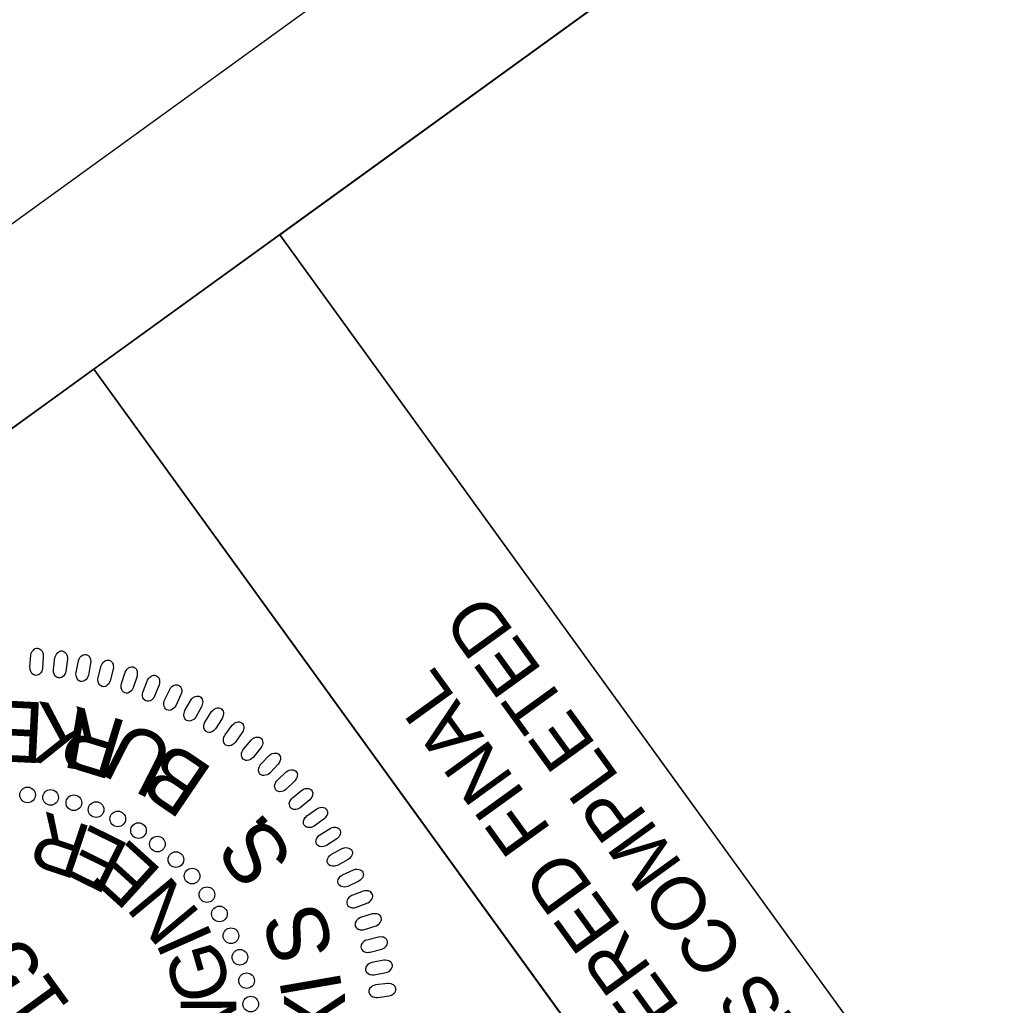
# Model space of a CAD drawing. Extents: x 474248 to 476123, y 501895 to 503900.
# Drawn here: x 474390.5 to 474491.3, y 503280.5 to 503381.5 of the extents above; entities that cross this region are included whole.
import ezdxf

# ---------------------------------------------------------------- set-up
doc = ezdxf.new("R2010")
doc.units = 0
for name, color, linetype in [('Scratch_Level_5', 7, 'Continuous'), ('Sheet Layout Plan Border', 7, 'Continuous'), ('Sheet PE Seal Cell', 7, 'Continuous'), ('Sheet Plan CELL', 7, 'Continuous'), ('Sheet Plot Border Outside CELL', 7, 'Continuous'), ('Sheet Sticker Exception Certification CELL', 7, 'Continuous'), ('Sheet Sticker Incomplete CELL', 7, 'Continuous')]:
    doc.layers.add(name, color=color, linetype=linetype)

msp = doc.modelspace()

# ---------------------------------------------------------------- linework, layer by layer
at = {"layer": 'Scratch_Level_5'}
msp.add_lwpolyline([(474627.91, 502772.46), (474393.92, 503095.62), (474534.48, 503197.42), (474417.16, 503359.44), (475062.24, 503826.52), (475162.27, 503688.38), (475227.09, 503735.31), (475493.16, 503367.85)], close=True, dxfattribs=at)
at = {"layer": 'Sheet Layout Plan Border'}
msp.add_lwpolyline([(475148.79, 502314.89), (475799.67, 502786.07), (475874.95, 502840.56), (475397.53, 503499.92), (475353.89, 503468.32), (475265.23, 503590.78), (475283.66, 503604.12), (475199.91, 503719.79), (475161.57, 503692.03), (475161.57, 503692.03), (475161.57, 503692.03), (475161.57, 503692.03), (475161.57, 503692.03), (475063.52, 503827.46), (474417.16, 503359.44), (474534.48, 503197.42), (474393.91, 503095.62), (475024.42, 502224.85)], close=True, dxfattribs=at)
at = {"layer": 'Sheet PE Seal Cell'}
for points in [[(474391.59, 503315.12), (474391.67, 503316.35), (474391.72, 503316.56), (474391.78, 503316.7), (474391.91, 503316.86), (474392.01, 503316.97), (474392.13, 503317.04), (474392.24, 503317.07), (474392.35, 503317.08), (474392.46, 503317.06), (474392.58, 503317.02), (474392.68, 503316.95), (474392.78, 503316.85), (474392.83, 503316.76), (474392.89, 503316.61), (474392.94, 503316.43), (474392.95, 503316.27), (474392.87, 503315.01), (474392.84, 503314.84), (474392.79, 503314.71), (474392.69, 503314.55), (474392.57, 503314.42), (474392.46, 503314.35), (474392.3, 503314.3), (474392.15, 503314.29), (474392.01, 503314.34), (474391.91, 503314.39), (474391.78, 503314.5), (474391.68, 503314.68), (474391.62, 503314.86), (474391.6, 503314.99)], [(474394, 503314.9), (474394.15, 503316.11), (474394.22, 503316.32), (474394.29, 503316.46), (474394.42, 503316.61), (474394.53, 503316.71), (474394.65, 503316.77), (474394.76, 503316.8), (474394.87, 503316.8), (474394.98, 503316.77), (474395.1, 503316.72), (474395.19, 503316.65), (474395.28, 503316.54), (474395.33, 503316.45), (474395.38, 503316.3), (474395.42, 503316.11), (474395.42, 503315.95), (474395.27, 503314.7), (474395.22, 503314.54), (474395.16, 503314.4), (474395.05, 503314.26), (474394.92, 503314.13), (474394.82, 503314.07), (474394.65, 503314.03), (474394.5, 503314.03), (474394.36, 503314.08), (474394.26, 503314.15), (474394.15, 503314.26), (474394.05, 503314.45), (474394.01, 503314.63), (474393.99, 503314.76)], [(474396.31, 503314.58), (474396.54, 503315.79), (474396.62, 503316), (474396.7, 503316.12), (474396.84, 503316.27), (474396.96, 503316.36), (474397.08, 503316.41), (474397.19, 503316.43), (474397.31, 503316.43), (474397.42, 503316.39), (474397.53, 503316.34), (474397.62, 503316.26), (474397.7, 503316.14), (474397.75, 503316.05), (474397.78, 503315.89), (474397.81, 503315.71), (474397.8, 503315.55), (474397.57, 503314.31), (474397.52, 503314.15), (474397.44, 503314.02), (474397.33, 503313.88), (474397.19, 503313.76), (474397.08, 503313.7), (474396.91, 503313.67), (474396.76, 503313.68), (474396.62, 503313.75), (474396.53, 503313.82), (474396.42, 503313.94), (474396.34, 503314.13), (474396.31, 503314.32), (474396.3, 503314.45)], [(474398.57, 503314.08), (474398.88, 503315.26), (474398.97, 503315.47), (474399.05, 503315.59), (474399.2, 503315.73), (474399.32, 503315.81), (474399.45, 503315.86), (474399.56, 503315.87), (474399.68, 503315.86), (474399.78, 503315.81), (474399.89, 503315.75), (474399.98, 503315.67), (474400.05, 503315.55), (474400.09, 503315.45), (474400.12, 503315.29), (474400.13, 503315.1), (474400.11, 503314.94), (474399.8, 503313.73), (474399.74, 503313.57), (474399.66, 503313.44), (474399.53, 503313.31), (474399.39, 503313.2), (474399.28, 503313.15), (474399.11, 503313.13), (474398.96, 503313.15), (474398.83, 503313.23), (474398.74, 503313.3), (474398.64, 503313.43), (474398.57, 503313.62), (474398.55, 503313.81), (474398.55, 503313.95)], [(474400.95, 503313.45), (474401.34, 503314.62), (474401.44, 503314.81), (474401.53, 503314.93), (474401.69, 503315.06), (474401.82, 503315.13), (474401.95, 503315.17), (474402.06, 503315.18), (474402.17, 503315.16), (474402.27, 503315.11), (474402.38, 503315.04), (474402.46, 503314.95), (474402.53, 503314.82), (474402.56, 503314.73), (474402.58, 503314.57), (474402.58, 503314.38), (474402.55, 503314.22), (474402.17, 503313.02), (474402.09, 503312.87), (474402.01, 503312.75), (474401.87, 503312.63), (474401.72, 503312.53), (474401.6, 503312.48), (474401.44, 503312.47), (474401.29, 503312.5), (474401.16, 503312.59), (474401.07, 503312.67), (474400.98, 503312.8), (474400.92, 503313), (474400.92, 503313.19), (474400.93, 503313.32)], [(474403.17, 503312.65), (474403.62, 503313.79), (474403.74, 503313.98), (474403.84, 503314.09), (474404.01, 503314.21), (474404.14, 503314.28), (474404.27, 503314.31), (474404.38, 503314.31), (474404.49, 503314.28), (474404.59, 503314.22), (474404.69, 503314.15), (474404.77, 503314.06), (474404.83, 503313.93), (474404.85, 503313.83), (474404.86, 503313.67), (474404.85, 503313.48), (474404.81, 503313.32), (474404.35, 503312.15), (474404.27, 503312), (474404.18, 503311.89), (474404.03, 503311.77), (474403.88, 503311.69), (474403.76, 503311.65), (474403.59, 503311.65), (474403.44, 503311.69), (474403.32, 503311.78), (474403.24, 503311.86), (474403.16, 503312), (474403.11, 503312.21), (474403.11, 503312.4), (474403.14, 503312.53)], [(474405.37, 503311.76), (474405.9, 503312.86), (474406.02, 503313.05), (474406.13, 503313.15), (474406.3, 503313.26), (474406.44, 503313.31), (474406.57, 503313.34), (474406.69, 503313.33), (474406.8, 503313.3), (474406.89, 503313.23), (474406.98, 503313.16), (474407.05, 503313.06), (474407.1, 503312.92), (474407.12, 503312.82), (474407.12, 503312.66), (474407.1, 503312.47), (474407.05, 503312.32), (474406.52, 503311.18), (474406.43, 503311.04), (474406.33, 503310.93), (474406.18, 503310.82), (474406.02, 503310.74), (474405.89, 503310.71), (474405.73, 503310.73), (474405.58, 503310.77), (474405.47, 503310.87), (474405.39, 503310.96), (474405.32, 503311.11), (474405.28, 503311.31), (474405.3, 503311.5), (474405.33, 503311.63)], [(474407.46, 503310.68), (474408.06, 503311.75), (474408.2, 503311.92), (474408.31, 503312.02), (474408.49, 503312.12), (474408.63, 503312.17), (474408.77, 503312.18), (474408.88, 503312.17), (474408.98, 503312.13), (474409.07, 503312.06), (474409.16, 503311.97), (474409.23, 503311.87), (474409.27, 503311.73), (474409.28, 503311.63), (474409.27, 503311.47), (474409.23, 503311.28), (474409.18, 503311.13), (474408.58, 503310.03), (474408.47, 503309.89), (474408.37, 503309.79), (474408.21, 503309.7), (474408.05, 503309.63), (474407.92, 503309.6), (474407.76, 503309.63), (474407.62, 503309.68), (474407.5, 503309.79), (474407.44, 503309.88), (474407.37, 503310.03), (474407.35, 503310.24), (474407.38, 503310.43), (474407.42, 503310.56)], [(474409.53, 503309.54), (474410.19, 503310.58), (474410.34, 503310.74), (474410.46, 503310.83), (474410.64, 503310.92), (474410.78, 503310.96), (474410.92, 503310.96), (474411.03, 503310.94), (474411.14, 503310.9), (474411.22, 503310.82), (474411.3, 503310.73), (474411.36, 503310.62), (474411.39, 503310.48), (474411.4, 503310.38), (474411.38, 503310.22), (474411.33, 503310.04), (474411.27, 503309.89), (474410.6, 503308.83), (474410.49, 503308.7), (474410.37, 503308.6), (474410.21, 503308.52), (474410.04, 503308.46), (474409.92, 503308.44), (474409.75, 503308.48), (474409.62, 503308.54), (474409.51, 503308.66), (474409.45, 503308.75), (474409.4, 503308.91), (474409.39, 503309.11), (474409.43, 503309.3), (474409.47, 503309.43)], [(474411.57, 503308.19), (474412.29, 503309.18), (474412.45, 503309.34), (474412.57, 503309.42), (474412.77, 503309.49), (474412.91, 503309.52), (474413.05, 503309.52), (474413.15, 503309.49), (474413.26, 503309.44), (474413.34, 503309.36), (474413.41, 503309.26), (474413.46, 503309.15), (474413.49, 503309.01), (474413.49, 503308.91), (474413.46, 503308.75), (474413.4, 503308.57), (474413.32, 503308.43), (474412.59, 503307.41), (474412.47, 503307.29), (474412.35, 503307.2), (474412.19, 503307.12), (474412.01, 503307.08), (474411.89, 503307.07), (474411.73, 503307.11), (474411.59, 503307.19), (474411.5, 503307.31), (474411.44, 503307.41), (474411.4, 503307.56), (474411.4, 503307.77), (474411.45, 503307.96), (474411.5, 503308.08)], [(474413.46, 503306.73), (474414.24, 503307.67), (474414.41, 503307.82), (474414.54, 503307.89), (474414.73, 503307.95), (474414.88, 503307.97), (474415.02, 503307.96), (474415.12, 503307.93), (474415.22, 503307.87), (474415.29, 503307.78), (474415.37, 503307.68), (474415.41, 503307.57), (474415.43, 503307.43), (474415.42, 503307.33), (474415.38, 503307.17), (474415.31, 503306.99), (474415.22, 503306.86), (474414.43, 503305.88), (474414.3, 503305.77), (474414.18, 503305.69), (474414.01, 503305.62), (474413.83, 503305.59), (474413.7, 503305.59), (474413.55, 503305.64), (474413.42, 503305.72), (474413.33, 503305.85), (474413.28, 503305.96), (474413.25, 503306.11), (474413.26, 503306.32), (474413.32, 503306.5), (474413.38, 503306.62)], [(474415.23, 503305.19), (474416.07, 503306.08), (474416.25, 503306.22), (474416.39, 503306.28), (474416.58, 503306.33), (474416.73, 503306.34), (474416.87, 503306.33), (474416.97, 503306.28), (474417.06, 503306.22), (474417.13, 503306.13), (474417.2, 503306.02), (474417.23, 503305.91), (474417.24, 503305.77), (474417.23, 503305.67), (474417.18, 503305.51), (474417.1, 503305.34), (474417, 503305.21), (474416.15, 503304.29), (474416.02, 503304.18), (474415.89, 503304.11), (474415.71, 503304.06), (474415.53, 503304.03), (474415.41, 503304.04), (474415.25, 503304.1), (474415.13, 503304.19), (474415.05, 503304.32), (474415.01, 503304.43), (474414.98, 503304.59), (474415.01, 503304.8), (474415.09, 503304.97), (474415.15, 503305.09)], [(474416.92, 503303.56), (474417.82, 503304.4), (474418, 503304.52), (474418.14, 503304.58), (474418.34, 503304.61), (474418.49, 503304.61), (474418.62, 503304.59), (474418.72, 503304.54), (474418.82, 503304.47), (474418.88, 503304.37), (474418.94, 503304.27), (474418.97, 503304.15), (474418.96, 503304), (474418.95, 503303.91), (474418.88, 503303.75), (474418.79, 503303.59), (474418.69, 503303.46), (474417.78, 503302.6), (474417.64, 503302.5), (474417.51, 503302.44), (474417.33, 503302.39), (474417.15, 503302.38), (474417.03, 503302.4), (474416.88, 503302.47), (474416.76, 503302.57), (474416.69, 503302.7), (474416.65, 503302.81), (474416.64, 503302.97), (474416.68, 503303.18), (474416.76, 503303.35), (474416.84, 503303.46)], [(474418.47, 503301.76), (474419.41, 503302.54), (474419.61, 503302.65), (474419.75, 503302.69), (474419.95, 503302.72), (474420.1, 503302.71), (474420.23, 503302.67), (474420.33, 503302.62), (474420.41, 503302.55), (474420.47, 503302.45), (474420.52, 503302.34), (474420.54, 503302.22), (474420.53, 503302.07), (474420.51, 503301.98), (474420.44, 503301.83), (474420.33, 503301.67), (474420.23, 503301.55), (474419.26, 503300.74), (474419.12, 503300.65), (474418.98, 503300.6), (474418.8, 503300.57), (474418.62, 503300.57), (474418.5, 503300.59), (474418.35, 503300.67), (474418.24, 503300.78), (474418.18, 503300.92), (474418.15, 503301.03), (474418.14, 503301.19), (474418.2, 503301.39), (474418.3, 503301.56), (474418.38, 503301.66)], [(474419.95, 503299.91), (474420.95, 503300.63), (474421.15, 503300.73), (474421.29, 503300.77), (474421.49, 503300.78), (474421.64, 503300.76), (474421.77, 503300.72), (474421.86, 503300.66), (474421.95, 503300.58), (474422, 503300.47), (474422.04, 503300.36), (474422.06, 503300.24), (474422.04, 503300.1), (474422.01, 503300), (474421.92, 503299.86), (474421.81, 503299.7), (474421.7, 503299.59), (474420.68, 503298.85), (474420.53, 503298.77), (474420.39, 503298.72), (474420.21, 503298.7), (474420.03, 503298.71), (474419.91, 503298.74), (474419.77, 503298.84), (474419.67, 503298.95), (474419.61, 503299.09), (474419.59, 503299.2), (474419.6, 503299.37), (474419.66, 503299.56), (474419.77, 503299.72), (474419.86, 503299.82)], [(474421.28, 503297.96), (474422.31, 503298.62), (474422.52, 503298.7), (474422.66, 503298.73), (474422.87, 503298.73), (474423.01, 503298.71), (474423.14, 503298.65), (474423.23, 503298.59), (474423.31, 503298.5), (474423.35, 503298.4), (474423.39, 503298.28), (474423.39, 503298.16), (474423.36, 503298.02), (474423.33, 503297.92), (474423.24, 503297.79), (474423.12, 503297.64), (474423, 503297.54), (474421.94, 503296.86), (474421.78, 503296.79), (474421.64, 503296.75), (474421.46, 503296.74), (474421.28, 503296.76), (474421.16, 503296.8), (474421.03, 503296.9), (474420.93, 503297.02), (474420.88, 503297.17), (474420.87, 503297.28), (474420.89, 503297.44), (474420.97, 503297.63), (474421.08, 503297.79), (474421.17, 503297.88)], [(474422.47, 503295.97), (474423.55, 503296.56), (474423.76, 503296.63), (474423.91, 503296.65), (474424.11, 503296.63), (474424.25, 503296.6), (474424.38, 503296.54), (474424.46, 503296.47), (474424.53, 503296.38), (474424.57, 503296.27), (474424.6, 503296.15), (474424.6, 503296.03), (474424.56, 503295.89), (474424.52, 503295.8), (474424.42, 503295.67), (474424.29, 503295.53), (474424.16, 503295.44), (474423.07, 503294.83), (474422.91, 503294.77), (474422.76, 503294.74), (474422.58, 503294.74), (474422.4, 503294.77), (474422.29, 503294.82), (474422.16, 503294.93), (474422.07, 503295.05), (474422.03, 503295.2), (474422.03, 503295.31), (474422.05, 503295.47), (474422.14, 503295.66), (474422.27, 503295.81), (474422.37, 503295.89)], [(474423.6, 503293.86), (474424.71, 503294.38), (474424.92, 503294.44), (474425.07, 503294.45), (474425.27, 503294.42), (474425.41, 503294.38), (474425.53, 503294.31), (474425.61, 503294.24), (474425.68, 503294.14), (474425.71, 503294.03), (474425.73, 503293.91), (474425.72, 503293.79), (474425.68, 503293.65), (474425.63, 503293.57), (474425.52, 503293.44), (474425.39, 503293.31), (474425.25, 503293.22), (474424.12, 503292.68), (474423.95, 503292.63), (474423.81, 503292.61), (474423.63, 503292.63), (474423.45, 503292.67), (474423.34, 503292.72), (474423.22, 503292.84), (474423.14, 503292.97), (474423.11, 503293.12), (474423.11, 503293.24), (474423.14, 503293.39), (474423.25, 503293.57), (474423.38, 503293.71), (474423.49, 503293.79)], [(474425.03, 503290.55), (474426.17, 503291), (474426.36, 503291.11), (474426.47, 503291.21), (474426.59, 503291.38), (474426.65, 503291.51), (474426.68, 503291.64), (474426.68, 503291.75), (474426.66, 503291.86), (474426.6, 503291.96), (474426.53, 503292.06), (474426.44, 503292.14), (474426.3, 503292.2), (474426.21, 503292.23), (474426.04, 503292.23), (474425.86, 503292.22), (474425.7, 503292.18), (474424.53, 503291.73), (474424.38, 503291.65), (474424.26, 503291.56), (474424.15, 503291.41), (474424.06, 503291.26), (474424.02, 503291.14), (474424.02, 503290.97), (474424.06, 503290.82), (474424.15, 503290.7), (474424.24, 503290.62), (474424.37, 503290.54), (474424.58, 503290.49), (474424.77, 503290.49), (474424.9, 503290.51)], [(474425.85, 503288.26), (474427.02, 503288.64), (474427.21, 503288.74), (474427.33, 503288.83), (474427.46, 503288.99), (474427.53, 503289.12), (474427.57, 503289.25), (474427.58, 503289.36), (474427.56, 503289.48), (474427.51, 503289.58), (474427.44, 503289.68), (474427.36, 503289.76), (474427.23, 503289.83), (474427.13, 503289.86), (474426.97, 503289.88), (474426.78, 503289.88), (474426.62, 503289.86), (474425.43, 503289.48), (474425.27, 503289.4), (474425.15, 503289.32), (474425.03, 503289.18), (474424.93, 503289.03), (474424.88, 503288.92), (474424.87, 503288.75), (474424.9, 503288.6), (474424.99, 503288.47), (474425.07, 503288.39), (474425.2, 503288.3), (474425.4, 503288.23), (474425.59, 503288.23), (474425.72, 503288.24)], [(474426.41, 503285.94), (474427.6, 503286.25), (474427.81, 503286.34), (474427.93, 503286.42), (474428.06, 503286.57), (474428.15, 503286.69), (474428.2, 503286.82), (474428.21, 503286.93), (474428.2, 503287.05), (474428.15, 503287.15), (474428.1, 503287.26), (474428.01, 503287.35), (474427.89, 503287.42), (474427.8, 503287.46), (474427.64, 503287.49), (474427.45, 503287.5), (474427.29, 503287.49), (474426.07, 503287.18), (474425.91, 503287.12), (474425.78, 503287.04), (474425.65, 503286.91), (474425.54, 503286.77), (474425.49, 503286.66), (474425.47, 503286.49), (474425.49, 503286.34), (474425.56, 503286.21), (474425.64, 503286.12), (474425.77, 503286.02), (474425.96, 503285.94), (474426.15, 503285.92), (474426.28, 503285.93)], [(474426.84, 503283.63), (474428.05, 503283.86), (474428.26, 503283.93), (474428.39, 503284.01), (474428.53, 503284.15), (474428.62, 503284.27), (474428.68, 503284.39), (474428.7, 503284.5), (474428.7, 503284.62), (474428.66, 503284.72), (474428.61, 503284.84), (474428.53, 503284.93), (474428.41, 503285.01), (474428.32, 503285.06), (474428.16, 503285.1), (474427.97, 503285.12), (474427.81, 503285.11), (474426.58, 503284.89), (474426.41, 503284.83), (474426.29, 503284.76), (474426.14, 503284.65), (474426.03, 503284.51), (474425.97, 503284.4), (474425.94, 503284.23), (474425.95, 503284.08), (474426.01, 503283.94), (474426.08, 503283.85), (474426.2, 503283.74), (474426.39, 503283.66), (474426.58, 503283.63), (474426.71, 503283.62)], [(474427.16, 503281.31), (474428.37, 503281.46), (474428.59, 503281.53), (474428.72, 503281.6), (474428.87, 503281.73), (474428.97, 503281.84), (474429.03, 503281.96), (474429.06, 503282.07), (474429.07, 503282.18), (474429.03, 503282.29), (474428.99, 503282.41), (474428.92, 503282.5), (474428.81, 503282.59), (474428.72, 503282.64), (474428.56, 503282.69), (474428.38, 503282.73), (474428.22, 503282.73), (474426.97, 503282.58), (474426.8, 503282.54), (474426.67, 503282.48), (474426.52, 503282.37), (474426.4, 503282.24), (474426.33, 503282.14), (474426.29, 503281.97), (474426.29, 503281.82), (474426.35, 503281.68), (474426.41, 503281.58), (474426.52, 503281.47), (474426.71, 503281.37), (474426.89, 503281.32), (474427.02, 503281.31)]]:
    msp.add_lwpolyline(points, close=True, dxfattribs=at)
for centre in [(474391.34, 503302.05), (474393.7, 503301.79), (474396.08, 503301.25), (474398.36, 503300.54), (474400.58, 503299.59), (474402.7, 503298.4), (474404.64, 503297.01), (474406.53, 503295.42), (474408.19, 503293.73), (474409.71, 503291.83), (474410.99, 503289.86), (474412.17, 503287.62), (474413.08, 503285.42), (474413.77, 503283.02), (474414.19, 503280.62)]:
    msp.add_circle(centre, 0.801, dxfattribs=at)
at = {"layer": 'Sheet Plan CELL'}
for points in [[(474276.58, 503257.68), (475156.32, 502042.7), (476006.78, 502658.5), (475127.06, 503873.46)], [(476006.78, 502658.5), (475156.35, 502042.69), (474393.91, 503095.62), (474515.45, 503183.63), (474398.14, 503345.66), (475127.06, 503873.46)], [(474365.67, 503198.69), (474307.02, 503279.67), (474398.14, 503345.66), (474456.8, 503264.68)]]:
    msp.add_lwpolyline(points, close=True, dxfattribs=at)
at = {"layer": 'Sheet Plot Border Outside CELL'}
msp.add_lwpolyline([(475235.74, 501894.66), (474248.41, 503258.24), (475135.32, 503900.43), (476122.66, 502536.85)], close=True, dxfattribs=at)
at = {"layer": 'Sheet Sticker Exception Certification CELL'}
for p, q in [((474398.14, 503345.66), (474417.17, 503359.45)), ((474398.14, 503345.66), (474417.17, 503359.45)), ((474417.16, 503359.44), (474534.48, 503197.42)), ((474417.16, 503359.44), (474534.48, 503197.42)), ((474515.45, 503183.63), (474398.13, 503345.66)), ((474515.45, 503183.63), (474398.13, 503345.66))]:
    msp.add_line(p, q, dxfattribs=at)

# ---------------------------------------------------------------- texts
at = {"layer": 'Sheet PE Seal Cell'}
for s, height, rotation, p in [('E', 6.24, 177.1721, (474393.18, 503311.51)), ('K', 6.24, 170.3264, (474397.91, 503310.73)), ('R', 6.24, 163.0514, (474401.74, 503309.51)), ('U', 6.24, 152.9516, (474406.78, 503307.1)), ('B', 6.24, 145.8347, (474410.53, 503304.61)), ('R', 5.67, 161.5674, (474398.08, 503298.72)), ('S', 6.24, 125.2865, (474418.78, 503295.52)), ('.', 6.24, 132.1321, (474416.45, 503298.82)), ('E', 5.67, 153.6276, (474401.97, 503296.87)), ('E', 5.67, 137.748, (474405.26, 503294.23)), ('N', 5.67, 129.8082, (474409.18, 503289.85)), ('46155', 6.236, 125.8852, (474401.37, 503272.89)), ('S', 6.24, 106.6913, (474422.83, 503285.96)), ('I', 5.67, 113.9286, (474410.42, 503287.34)), ('SEAL', 6.236, 125.8852, (474393.45, 503270.05)), ('G', 5.67, 105.9888, (474412.35, 503281.79)), ('I', 6.24, 99.8456, (474423.6, 503282.01)), ('N', 5.67, 90.1092, (474412.71, 503276.01)), ('X', 6.24, 90.8983, (474423.91, 503276.36))]:
    msp.add_text(s, height=height, rotation=rotation, dxfattribs=at).set_placement(p)
at = {"layer": 'Sheet Sticker Exception Certification CELL'}
for s, p in [('UNLESS ALL SIGNATURES COMPLETED', (474521.57, 503207.82)), ('UNLESS ALL SIGNATURES COMPLETED', (474521.57, 503207.82)), ('DOCUMENT NOT CONSIDERED FINAL', (474511.47, 503206.77)), ('DOCUMENT NOT CONSIDERED FINAL', (474511.47, 503206.77))]:
    msp.add_text(s, height=5.5, rotation=125.9074, dxfattribs=at).set_placement(p)
at = {"layer": 'Sheet Sticker Incomplete CELL'}
for s, height, p in [('INCOMPLETE PLANS', 11.52, (474439.61, 503172.53)), ('DO NOT USE FOR R/W ACQUISITION', 5.76, (474443.33, 503179.24))]:
    msp.add_text(s, height=height, rotation=125.9074, dxfattribs=at).set_placement(p)

doc.saveas('drawing.dxf')
